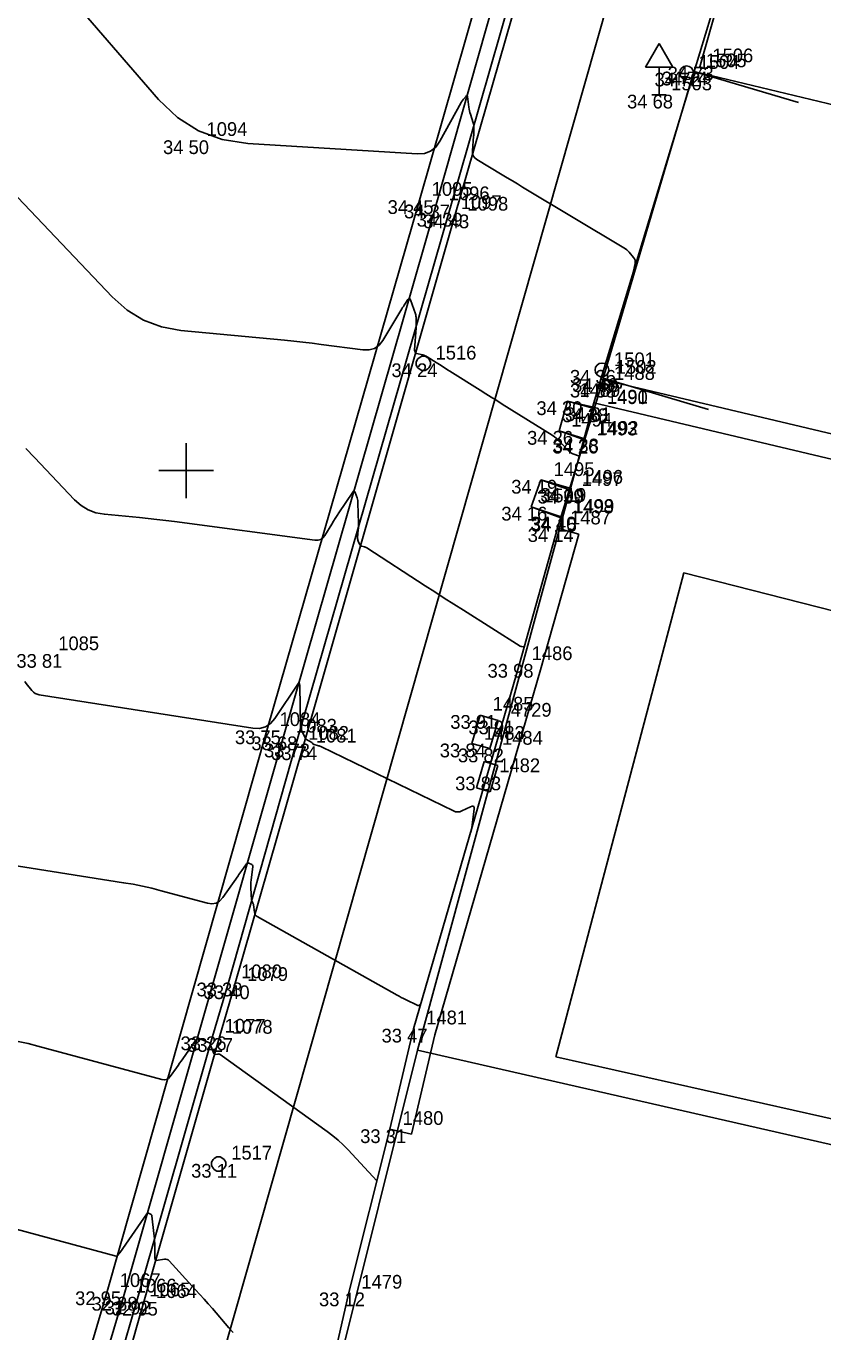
# Model space of a CAD drawing. Extents: x -702257 to -701487, y -1009871 to -1008841.
# Drawn here: x -701727.92 to -701713.41, y -1009265.68 to -1009241.91 of the extents above; entities that cross this region are included whole.
import ezdxf

# ---------------------------------------------------------------- set-up
doc = ezdxf.new("R2010")
doc.units = 0
for name, color, linetype in [('Ex_Major Contours', 7, 'Continuous'), ('Ex_Minor Contours', 7, 'Continuous'), ('Z_body', 7, 'Continuous'), ('Z_body_cisla', 7, 'Continuous'), ('Z_body_vysky_redukovane', 7, 'Continuous'), ('Z_budova', 7, 'Continuous'), ('Z_dopravni_znacky', 7, 'Continuous'), ('Z_hektometricka_sit', 7, 'Continuous'), ('Z_katastr_hranice', 7, 'Continuous'), ('Z_katastr_vnitrni_kresba', 7, 'Continuous'), ('Z_komunikace', 7, 'Continuous'), ('Z_obruba', 7, 'Continuous'), ('Z_pilire', 7, 'Continuous'), ('Z_ploty', 7, 'Continuous'), ('Z_rozhranni', 7, 'Continuous'), ('Z_site_kanalizace_znaky', 7, 'Continuous'), ('Z_site_vodovod_znaky', 7, 'Continuous'), ('Z_vstupy', 7, 'Continuous'), ('Z_zlabek', 7, 'Continuous')]:
    doc.layers.add(name, color=color, linetype=linetype)

# ---------------------------------------------------------------- blocks, each defined once
blk = doc.blocks.new('POINT_DISPLAY')
blk.add_line((0, 0), (0, 0))
blk = doc.blocks.new('Z15')
blk.add_circle((0, 0), 0.125)
blk = doc.blocks.new('Z666')
for p, q in [((-0.25, 0.13), (-0.25, -0.13)), ((0.25, 0.13), (-0.25, 0.13)), ((0.25, -0.13), (0.25, 0.13)), ((-0.25, -0.13), (0.25, -0.13))]:
    blk.add_line(p, q)
blk = doc.blocks.new('Z614')
for p, q in [((-0.13, 0.03), (-0.1, 0.08)), ((-0.13, -0.03), (-0.13, 0.03)), ((-0.1, 0.08), (-0.08, 0.1)), ((-0.08, 0.1), (-0.03, 0.13)), ((-0.03, 0.13), (0.03, 0.13)), ((0.03, 0.13), (0.08, 0.1)), ((0.08, 0.1), (0.1, 0.08)), ((0.1, 0.08), (0.13, 0.03)), ((0.13, 0.03), (0.13, -0.03)), ((-0.1, -0.08), (-0.13, -0.03)), ((-0.08, -0.1), (-0.1, -0.08)), ((-0.03, -0.13), (-0.08, -0.1)), ((0.03, -0.13), (-0.03, -0.13)), ((0.08, -0.1), (0.03, -0.13)), ((0.1, -0.08), (0.08, -0.1)), ((0.13, -0.03), (0.1, -0.08))]:
    blk.add_line(p, q)
blk = doc.blocks.new('Z527')
for p, q in [((0, 0.93), (-0.25, 0.5)), ((0.25, 0.5), (0, 0.93)), ((-0.25, 0.5), (0.25, 0.5)), ((0, 0), (0, 0.5)), ((-0.13, 0), (0.13, 0))]:
    blk.add_line(p, q)

msp = doc.modelspace()

# ---------------------------------------------------------------- linework, layer by layer
at = {"layer": 'Ex_Major Contours'}
for points in [[(-701718.844, -1009253.211), (-701718.891, -1009253.204), (-701718.899, -1009253.203), (-701718.906, -1009253.201), (-701718.913, -1009253.198), (-701718.92, -1009253.194), (-701719.952, -1009252.541), (-701720.127, -1009252.431), (-701720.3, -1009252.32), (-701720.474, -1009252.209), (-701720.647, -1009252.097), (-701721.711, -1009251.409), (-701721.721, -1009251.403), (-701721.732, -1009251.397), (-701721.743, -1009251.393), (-701721.755, -1009251.39), (-701721.802, -1009251.378), (-701721.814, -1009251.374), (-701721.823, -1009251.368), (-701721.831, -1009251.36), (-701721.837, -1009251.35), (-701721.868, -1009251.285), (-701721.874, -1009251.27), (-701721.877, -1009251.255), (-701721.879, -1009251.239), (-701721.879, -1009251.223), (-701721.867, -1009251.078), (-701721.865, -1009251.048), (-701721.864, -1009251.018), (-701721.864, -1009250.988), (-701721.864, -1009250.959), (-701721.872, -1009250.596), (-701721.874, -1009250.571), (-701721.877, -1009250.545), (-701721.883, -1009250.521), (-701721.89, -1009250.496), (-701721.924, -1009250.399), (-701721.933, -1009250.381), (-701721.944, -1009250.374), (-701721.956, -1009250.378), (-701721.969, -1009250.393), (-701722.221, -1009250.771), (-701722.254, -1009250.821), (-701722.287, -1009250.872), (-701722.319, -1009250.923), (-701722.35, -1009250.974), (-701722.475, -1009251.18), (-701722.51, -1009251.225), (-701722.551, -1009251.254), (-701722.6, -1009251.268), (-701722.657, -1009251.268), (-701725.213, -1009250.93), (-701725.372, -1009250.91), (-701725.532, -1009250.891), (-701725.691, -1009250.873), (-701725.851, -1009250.857), (-701726.49, -1009250.796), (-701726.643, -1009250.768), (-701726.785, -1009250.715), (-701726.914, -1009250.637), (-701727.031, -1009250.533), (-701727.762, -1009249.765), (-701727.918, -1009249.597)], [(-701730.306, -1009263.211), (-701726.274, -1009264.298), (-701726.266, -1009264.299), (-701726.26, -1009264.297), (-701726.254, -1009264.294), (-701726.249, -1009264.288), (-701726.22, -1009264.248), (-701726.211, -1009264.235), (-701725.715, -1009263.527), (-701725.709, -1009263.52), (-701725.702, -1009263.516), (-701725.694, -1009263.516), (-701725.685, -1009263.518), (-701725.647, -1009263.535), (-701725.639, -1009263.54), (-701725.632, -1009263.546), (-701725.628, -1009263.554), (-701725.626, -1009263.564), (-701725.587, -1009263.886), (-701725.582, -1009263.932), (-701725.578, -1009263.978), (-701725.575, -1009264.025), (-701725.574, -1009264.071), (-701725.569, -1009264.343), (-701725.568, -1009264.347), (-701725.568, -1009264.351), (-701725.567, -1009264.355), (-701725.565, -1009264.358), (-701725.559, -1009264.373), (-701725.557, -1009264.376), (-701725.555, -1009264.378), (-701725.552, -1009264.379), (-701725.548, -1009264.379), (-701725.398, -1009264.354), (-701725.372, -1009264.353), (-701725.349, -1009264.358), (-701725.328, -1009264.368), (-701725.309, -1009264.385), (-701724.828, -1009264.91), (-701724.751, -1009264.995), (-701724.674, -1009265.081), (-701724.598, -1009265.167), (-701724.522, -1009265.254), (-701724.221, -1009265.601), (-701724.144, -1009265.686)]]:
    msp.add_lwpolyline(points, dxfattribs=at)
at = {"layer": 'Ex_Minor Contours'}
for points in [[(-701727.258, -1009241.213), (-701725.503, -1009243.245), (-701725.16, -1009243.575), (-701724.775, -1009243.819), (-701724.348, -1009243.977), (-701723.878, -1009244.049), (-701720.793, -1009244.236), (-701720.663, -1009244.228), (-701720.55, -1009244.188), (-701720.456, -1009244.114), (-701720.38, -1009244.008), (-701719.996, -1009243.304), (-701719.987, -1009243.288), (-701719.977, -1009243.272), (-701719.966, -1009243.257), (-701719.954, -1009243.242), (-701719.905, -1009243.185), (-701719.894, -1009243.175), (-701719.886, -1009243.173), (-701719.88, -1009243.179), (-701719.876, -1009243.194), (-701719.854, -1009243.386), (-701719.849, -1009243.42), (-701719.843, -1009243.452), (-701719.835, -1009243.485), (-701719.825, -1009243.517), (-701719.774, -1009243.67), (-701719.768, -1009243.69), (-701719.764, -1009243.71), (-701719.762, -1009243.73), (-701719.761, -1009243.75), (-701719.762, -1009243.832), (-701719.763, -1009243.853), (-701719.764, -1009243.873), (-701719.765, -1009243.894), (-701719.766, -1009243.914), (-701719.789, -1009244.184), (-701719.787, -1009244.233), (-701719.773, -1009244.275), (-701719.747, -1009244.311), (-701719.708, -1009244.341), (-701719.245, -1009244.619), (-701719.153, -1009244.674), (-701719.061, -1009244.73), (-701718.969, -1009244.785), (-701718.877, -1009244.84), (-701717.029, -1009245.946), (-701717.003, -1009245.963), (-701716.978, -1009245.982), (-701716.956, -1009246.003), (-701716.935, -1009246.026), (-701716.855, -1009246.122), (-701716.838, -1009246.146), (-701716.828, -1009246.173), (-701716.825, -1009246.201), (-701716.828, -1009246.23), (-701716.925, -1009246.679)], [(-701717.838, -1009249.737), (-701717.963, -1009249.694), (-701717.984, -1009249.685), (-701718.002, -1009249.674), (-701718.02, -1009249.662), (-701718.035, -1009249.646), (-701718.194, -1009249.475), (-701718.227, -1009249.442), (-701718.261, -1009249.412), (-701718.297, -1009249.384), (-701718.336, -1009249.358), (-701719.245, -1009248.79), (-701719.345, -1009248.727), (-701719.445, -1009248.665), (-701719.545, -1009248.602), (-701719.645, -1009248.54), (-701720.202, -1009248.191), (-701720.243, -1009248.165), (-701720.285, -1009248.139), (-701720.388, -1009248.073), (-701720.451, -1009248.034), (-701720.612, -1009247.931), (-701720.631, -1009247.92), (-701720.651, -1009247.911), (-701720.671, -1009247.903), (-701720.693, -1009247.897), (-701720.809, -1009247.868), (-701720.816, -1009247.866), (-701720.821, -1009247.863), (-701720.825, -1009247.859), (-701720.828, -1009247.853), (-701720.84, -1009247.829), (-701720.842, -1009247.822), (-701720.844, -1009247.816), (-701720.845, -1009247.809), (-701720.845, -1009247.803), (-701720.813, -1009247.401), (-701720.812, -1009247.38), (-701720.811, -1009247.359), (-701720.81, -1009247.338), (-701720.811, -1009247.317), (-701720.813, -1009247.232), (-701720.814, -1009247.211), (-701720.817, -1009247.19), (-701720.821, -1009247.169), (-701720.827, -1009247.149), (-701720.917, -1009246.891), (-701720.926, -1009246.873), (-701720.936, -1009246.866), (-701720.948, -1009246.87), (-701720.962, -1009246.886), (-701721.018, -1009246.97), (-701721.032, -1009246.991), (-701721.046, -1009247.013), (-701721.059, -1009247.034), (-701721.072, -1009247.056), (-701721.42, -1009247.631), (-701721.489, -1009247.719), (-701721.573, -1009247.778), (-701721.671, -1009247.806), (-701721.783, -1009247.806), (-701722.542, -1009247.705), (-701722.709, -1009247.684), (-701722.875, -1009247.664), (-701723.042, -1009247.646), (-701723.209, -1009247.629), (-701725.095, -1009247.449), (-701725.45, -1009247.384), (-701725.778, -1009247.261), (-701726.077, -1009247.079), (-701726.347, -1009246.839), (-701728.649, -1009244.422)], [(-701718.013, -1009250.329), (-701718.016, -1009250.326), (-701718.016, -1009250.327), (-701718.107, -1009250.622), (-701718.129, -1009250.695), (-701718.172, -1009250.836), (-701718.174, -1009250.842), (-701718.176, -1009250.852)], [(-701727.938, -1009253.84), (-701727.913, -1009253.873), (-701727.81, -1009254.004), (-701727.783, -1009254.034), (-701727.751, -1009254.057), (-701727.716, -1009254.073), (-701727.677, -1009254.083), (-701723.789, -1009254.69), (-701723.667, -1009254.694), (-701723.558, -1009254.665), (-701723.464, -1009254.605), (-701723.384, -1009254.512), (-701722.954, -1009253.867), (-701722.951, -1009253.864), (-701722.949, -1009253.863), (-701722.946, -1009253.865), (-701722.944, -1009253.869), (-701722.937, -1009253.89), (-701722.935, -1009253.895), (-701722.934, -1009253.901), (-701722.933, -1009253.906), (-701722.933, -1009253.912), (-701722.916, -1009254.673), (-701722.916, -1009254.682), (-701722.917, -1009254.69), (-701722.917, -1009254.695), (-701722.915, -1009254.699), (-701722.83, -1009254.879), (-701722.829, -1009254.88), (-701722.825, -1009254.881), (-701722.778, -1009254.912), (-701722.757, -1009254.925), (-701722.714, -1009254.952), (-701722.71, -1009254.955), (-701722.706, -1009254.958), (-701722.703, -1009254.961), (-701722.7, -1009254.965), (-701722.687, -1009254.979), (-701722.684, -1009254.983), (-701722.68, -1009254.985), (-701722.676, -1009254.987), (-701722.671, -1009254.989), (-701722.592, -1009255.008), (-701722.578, -1009255.012), (-701722.564, -1009255.017), (-701722.55, -1009255.022), (-701722.536, -1009255.028), (-701720.135, -1009256.195), (-701720.097, -1009256.209), (-701720.058, -1009256.213), (-701720.019, -1009256.209), (-701719.98, -1009256.194), (-701719.825, -1009256.118), (-701719.792, -1009256.107), (-701719.77, -1009256.111), (-701719.759, -1009256.131), (-701719.758, -1009256.166), (-701719.798, -1009256.495), (-701719.799, -1009256.505), (-701719.801, -1009256.514), (-701719.803, -1009256.524), (-701719.805, -1009256.533), (-701719.818, -1009256.59)], [(-701720.748, -1009259.778), (-701720.746, -1009259.767), (-701720.742, -1009259.732), (-701720.742, -1009259.728), (-701720.743, -1009259.726), (-701720.746, -1009259.726), (-701720.749, -1009259.727), (-701720.766, -1009259.735), (-701720.77, -1009259.737), (-701720.774, -1009259.737), (-701720.778, -1009259.737), (-701720.782, -1009259.735), (-701721.006, -1009259.626), (-701721.045, -1009259.607), (-701721.083, -1009259.588), (-701721.121, -1009259.568), (-701721.158, -1009259.547), (-701723.708, -1009258.116), (-701723.728, -1009258.102), (-701723.743, -1009258.084), (-701723.753, -1009258.063), (-701723.758, -1009258.04), (-701723.775, -1009257.903), (-701723.776, -1009257.895), (-701723.778, -1009257.887), (-701723.781, -1009257.88), (-701723.785, -1009257.872), (-701723.8, -1009257.843), (-701723.804, -1009257.836), (-701723.807, -1009257.828), (-701723.808, -1009257.82), (-701723.809, -1009257.812), (-701723.825, -1009257.603), (-701723.826, -1009257.566), (-701723.826, -1009257.528), (-701723.824, -1009257.491), (-701723.82, -1009257.453), (-701723.787, -1009257.208), (-701723.787, -1009257.195), (-701723.79, -1009257.184), (-701723.797, -1009257.175), (-701723.808, -1009257.169), (-701723.859, -1009257.146), (-701723.871, -1009257.143), (-701723.882, -1009257.144), (-701723.892, -1009257.149), (-701723.901, -1009257.158), (-701723.987, -1009257.282), (-701724.004, -1009257.306), (-701724.022, -1009257.33), (-701724.039, -1009257.355), (-701724.056, -1009257.379), (-701724.335, -1009257.773), (-701724.392, -1009257.835), (-701724.457, -1009257.872), (-701724.531, -1009257.885), (-701724.614, -1009257.874), (-701725.455, -1009257.647), (-701725.624, -1009257.604), (-701725.795, -1009257.565), (-701725.967, -1009257.531), (-701726.139, -1009257.502), (-701728.206, -1009257.179)], [(-701728.058, -1009260.391), (-701727.88, -1009260.431), (-701727.703, -1009260.477), (-701725.444, -1009261.086), (-701725.399, -1009261.092), (-701725.358, -1009261.085), (-701725.323, -1009261.064), (-701725.292, -1009261.031), (-701725.178, -1009260.87), (-701725.149, -1009260.83), (-701725.121, -1009260.789), (-701725.093, -1009260.749), (-701725.064, -1009260.709), (-701724.83, -1009260.374), (-701724.811, -1009260.353), (-701724.789, -1009260.342), (-701724.764, -1009260.34), (-701724.736, -1009260.348), (-701724.566, -1009260.423), (-701724.563, -1009260.425), (-701724.562, -1009260.429), (-701724.561, -1009260.441), (-701724.56, -1009260.454), (-701724.559, -1009260.459), (-701724.494, -1009260.61), (-701724.489, -1009260.619), (-701724.482, -1009260.624), (-701724.474, -1009260.627), (-701724.465, -1009260.627), (-701724.422, -1009260.62), (-701724.412, -1009260.619), (-701724.402, -1009260.62), (-701724.393, -1009260.623), (-701724.384, -1009260.629), (-701722.434, -1009262.03), (-701722.332, -1009262.107), (-701722.234, -1009262.188), (-701722.141, -1009262.275), (-701722.051, -1009262.366), (-701721.527, -1009262.928)]]:
    msp.add_lwpolyline(points, dxfattribs=at)
at = {"layer": 'Z_budova'}
for p, q in [((-701715.76, -1009242.74), (-701717.41, -1009248.32)), ((-701713.85, -1009243.3), (-701715.76, -1009242.74)), ((-701717.41, -1009248.32), (-701715.49, -1009248.89))]:
    msp.add_line(p, q, dxfattribs=at)
at = {"layer": 'Z_hektometricka_sit'}
for p, q in [((-701725, -1009249.5), (-701725, -1009250.5)), ((-701725, -1009249.5), (-701725, -1009250.5)), ((-701725.5, -1009250), (-701724.5, -1009250)), ((-701725.5, -1009250), (-701724.5, -1009250))]:
    msp.add_line(p, q, dxfattribs=at)
at = {"layer": 'Z_katastr_hranice'}
for p, q in [((-701705.38, -1009199.53), (-701735.58, -1009305.62)), ((-701714.04, -1009237.1), (-701715.75, -1009242.74)), ((-701715.75, -1009242.74), (-701717.45, -1009248.34)), ((-701717.45, -1009248.34), (-701717.58, -1009248.77)), ((-701717.58, -1009248.77), (-701720.79, -1009260.55)), ((-701717.58, -1009248.77), (-701702.1, -1009252.43)), ((-701720.79, -1009260.55), (-701723.82, -1009272.69)), ((-701720.79, -1009260.55), (-701694.55, -1009266.54))]:
    msp.add_line(p, q, dxfattribs=at)
at = {"layer": 'Z_katastr_vnitrni_kresba'}
for p, q in [((-701715.75, -1009242.74), (-701708.04, -1009244.58)), ((-701701.98, -1009252), (-701717.45, -1009248.34)), ((-701715.94, -1009251.86), (-701718.27, -1009260.67)), ((-701710.58, -1009253.23), (-701715.94, -1009251.86)), ((-701718.27, -1009260.67), (-701703.41, -1009264.01))]:
    msp.add_line(p, q, dxfattribs=at)
at = {"layer": 'Z_komunikace'}
for p, q in [((-701719.01, -1009241.09), (-701720.22, -1009245.31)), ((-701723, -1009254.97), (-701720.22, -1009245.31)), ((-701724.23, -1009259.32), (-701723, -1009254.97)), ((-701724.52, -1009260.3), (-701724.23, -1009259.32)), ((-701725.9, -1009265.11), (-701724.52, -1009260.3)), ((-701725.9, -1009265.11), (-701727.56, -1009270.85))]:
    msp.add_line(p, q, dxfattribs=at)
at = {"layer": 'Z_obruba'}
for p, q in [((-701720.1, -1009245.34), (-701718.89, -1009241.13)), ((-701720.1, -1009245.34), (-701722.87, -1009255.02)), ((-701722.87, -1009255.02), (-701724.12, -1009259.37)), ((-701724.12, -1009259.37), (-701724.4, -1009260.33)), ((-701724.4, -1009260.33), (-701725.77, -1009265.13)), ((-701727.43, -1009270.89), (-701725.77, -1009265.13))]:
    msp.add_line(p, q, dxfattribs=at)
at = {"layer": 'Z_pilire'}
for p, q in [((-701719.65, -1009254.45), (-701719.8, -1009254.97)), ((-701719.65, -1009254.45), (-701719.32, -1009254.55)), ((-701719.47, -1009255.06), (-701719.32, -1009254.55)), ((-701719.8, -1009254.97), (-701719.47, -1009255.06))]:
    msp.add_line(p, q, dxfattribs=at)
at = {"layer": 'Z_ploty'}
for p, q in [((-701717.43, -1009248.42), (-701717.41, -1009248.32)), ((-701717.09, -1009248.5), (-701717.43, -1009248.42)), ((-701717.09, -1009248.5), (-701717.07, -1009248.42)), ((-701718.24, -1009251.05), (-701718.93, -1009253.52)), ((-701717.85, -1009251.16), (-701718.24, -1009251.05)), ((-701717.85, -1009251.16), (-701718.55, -1009253.63)), ((-701718.93, -1009253.52), (-701720.86, -1009260.16)), ((-701718.55, -1009253.63), (-701720.47, -1009260.27)), ((-701720.86, -1009260.16), (-701721.29, -1009261.99)), ((-701720.47, -1009260.27), (-701720.9, -1009262.08)), ((-701720.9, -1009262.08), (-701721.29, -1009261.99)), ((-701722.04, -1009264.96), (-701722.37, -1009266.42))]:
    msp.add_line(p, q, dxfattribs=at)
at = {"layer": 'Z_rozhranni'}
for p, q in [((-701718.21, -1009249.28), (-701718.06, -1009248.74)), ((-701718.06, -1009248.74), (-701717.57, -1009248.87)), ((-701717.56, -1009248.85), (-701718.06, -1009248.74)), ((-701718.21, -1009249.28), (-701717.75, -1009249.44)), ((-701717.74, -1009249.42), (-701718.21, -1009249.28)), ((-701718.72, -1009250.66), (-701718.54, -1009250.17)), ((-701718.54, -1009250.17), (-701718.02, -1009250.35)), ((-701718.01, -1009250.32), (-701718.54, -1009250.17)), ((-701718.17, -1009250.84), (-701718.72, -1009250.66)), ((-701718.18, -1009250.86), (-701718.72, -1009250.66))]:
    msp.add_line(p, q, dxfattribs=at)
at = {"layer": 'Z_vstupy'}
for p, q in [((-701715.65, -1009242.65), (-701715.3, -1009241.43)), ((-701717.43, -1009248.42), (-701718.24, -1009251.05)), ((-701721.29, -1009261.99), (-701722.04, -1009264.96))]:
    msp.add_line(p, q, dxfattribs=at)
at = {"layer": 'Z_zlabek'}
for p, q in [((-701720.75, -1009245.08), (-701718.2, -1009236.15)), ((-701717.91, -1009236.22), (-701720.45, -1009245.16)), ((-701720.75, -1009245.08), (-701723.53, -1009254.73)), ((-701723.23, -1009254.84), (-701720.45, -1009245.16)), ((-701723.53, -1009254.73), (-701726.44, -1009264.94)), ((-701726.14, -1009265.04), (-701723.23, -1009254.84)), ((-701726.44, -1009264.94), (-701728.12, -1009270.67)), ((-701727.88, -1009270.78), (-701726.14, -1009265.04))]:
    msp.add_line(p, q, dxfattribs=at)

# ---------------------------------------------------------------- block references
at = {"layer": 'Z_body'}
for p in [(-701715.89, -1009242.76), (-701715.76, -1009242.74), (-701715.65, -1009242.65), (-701716.39, -1009243.16), (-701724.86, -1009243.99), (-701720.75, -1009245.08), (-701720.45, -1009245.16), (-701720.22, -1009245.31), (-701720.1, -1009245.34), (-701720.68, -1009248.05), (-701717.43, -1009248.17), (-701717.43, -1009248.42), (-701717.41, -1009248.32), (-701718.06, -1009248.74), (-701717.57, -1009248.87), (-701717.56, -1009248.85), (-701718.21, -1009249.28), (-701717.75, -1009249.44), (-701717.74, -1009249.42), (-701718.54, -1009250.17), (-701718.02, -1009250.35), (-701718.01, -1009250.32), (-701718.72, -1009250.66), (-701718.18, -1009250.86), (-701718.17, -1009250.84), (-701718.24, -1009251.05), (-701727.55, -1009253.34), (-701718.93, -1009253.52), (-701719.65, -1009254.45), (-701719.32, -1009254.55), (-701723.53, -1009254.73), (-701723.23, -1009254.84), (-701723, -1009254.97), (-701722.87, -1009255.02), (-701719.8, -1009254.97), (-701719.47, -1009255.06), (-701719.52, -1009255.57), (-701724.23, -1009259.32), (-701724.12, -1009259.37), (-701720.86, -1009260.16), (-701724.52, -1009260.3), (-701724.4, -1009260.33), (-701721.29, -1009261.99), (-701724.41, -1009262.62), (-701726.44, -1009264.94), (-701726.14, -1009265.04), (-701725.9, -1009265.11), (-701725.77, -1009265.13), (-701722.04, -1009264.96)]:
    msp.add_blockref('POINT_DISPLAY', p, dxfattribs=at)
at = {"layer": 'Z_dopravni_znacky'}
msp.add_blockref('Z527', (-701716.39, -1009243.16), dxfattribs=at)
at = {"layer": 'Z_pilire', "rotation": 73.8}
msp.add_blockref('Z666', (-701719.52, -1009255.57), dxfattribs=at)
at = {"layer": 'Z_site_kanalizace_znaky'}
for p in [(-701715.89, -1009242.76), (-701717.43, -1009248.17)]:
    msp.add_blockref('Z15', p, dxfattribs=at)
at = {"layer": 'Z_site_vodovod_znaky'}
for p in [(-701720.68, -1009248.05), (-701724.41, -1009262.62)]:
    msp.add_blockref('Z614', p, dxfattribs=at)

# ---------------------------------------------------------------- texts
at = {"layer": 'Z_body_cisla'}
for s, p in [('1506', (-701715.42, -1009242.57)), ('1504', (-701715.67, -1009242.69)), ('1505', (-701715.54, -1009242.66)), ('1503', (-701716.17, -1009243.08)), ('1094', (-701724.63, -1009243.91)), ('1095', (-701720.53, -1009245)), ('1096', (-701720.22, -1009245.08)), ('1097', (-701720, -1009245.24)), ('1098', (-701719.88, -1009245.27)), ('1516', (-701720.46, -1009247.98)), ('1501', (-701717.21, -1009248.1)), ('1502', (-701717.18, -1009248.24)), ('1488', (-701717.21, -1009248.35)), ('1489', (-701717.84, -1009248.66)), ('1491', (-701717.34, -1009248.78)), ('1490', (-701717.34, -1009248.79)), ('1494', (-701717.99, -1009249.2)), ('1493', (-701717.53, -1009249.36)), ('1492', (-701717.51, -1009249.35)), ('1495', (-701718.31, -1009250.1)), ('1497', (-701717.8, -1009250.28)), ('1496', (-701717.79, -1009250.24)), ('1500', (-701718.5, -1009250.58)), ('1498', (-701717.96, -1009250.78)), ('1499', (-701717.95, -1009250.77)), ('1487', (-701718.01, -1009250.98)), ('1085', (-701727.33, -1009253.27)), ('1486', (-701718.71, -1009253.45)), ('1485', (-701719.42, -1009254.37)), ('4729', (-701719.09, -1009254.48)), ('1084', (-701723.3, -1009254.65)), ('1083', (-701723, -1009254.77)), ('1082', (-701722.78, -1009254.9)), ('1081', (-701722.64, -1009254.95)), ('1483', (-701719.58, -1009254.9)), ('1484', (-701719.25, -1009254.99)), ('1482', (-701719.3, -1009255.49)), ('1080', (-701724, -1009259.24)), ('1079', (-701723.89, -1009259.29)), ('1481', (-701720.63, -1009260.08)), ('1077', (-701724.3, -1009260.23)), ('1078', (-701724.17, -1009260.25)), ('1480', (-701721.06, -1009261.91)), ('1517', (-701724.18, -1009262.54)), ('1067', (-701726.21, -1009264.86)), ('1479', (-701721.81, -1009264.89)), ('1066', (-701725.92, -1009264.96)), ('1065', (-701725.67, -1009265.03)), ('1064', (-701725.55, -1009265.06))]:
    msp.add_text(s, height=0.25, dxfattribs=at).set_placement(p)
at = {"layer": 'Z_body_vysky_redukovane'}
for s, p in [('34 72', (-701716.473, -1009243.01)), ('34 74', (-701716.343, -1009242.99)), ('34 73', (-701716.233, -1009242.9)), ('34 68', (-701716.973, -1009243.41)), ('34 50', (-701725.422, -1009244.24)), ('34 45', (-701721.333, -1009245.33)), ('34 37', (-701721.033, -1009245.41)), ('34 39', (-701720.803, -1009245.56)), ('34 43', (-701720.683, -1009245.59)), ('34 24', (-701721.263, -1009248.3)), ('34 36', (-701718.013, -1009248.42)), ('34 38', (-701718.013, -1009248.67)), ('34 40', (-701717.973, -1009248.57)), ('34 30', (-701718.623, -1009248.99)), ('34 38', (-701718.153, -1009249.12)), ('34 31', (-701718.102, -1009249.1)), ('34 26', (-701718.793, -1009249.53)), ('34 26', (-701718.333, -1009249.69)), ('34 38', (-701718.323, -1009249.67)), ('34 19', (-701719.082, -1009250.42)), ('34 39', (-701718.603, -1009250.6)), ('34 19', (-701718.552, -1009250.57)), ('34 16', (-701719.262, -1009250.91)), ('34 40', (-701718.733, -1009251.09)), ('34 15', (-701718.722, -1009251.11)), ('34 14', (-701718.782, -1009251.3)), ('33 81', (-701728.092, -1009253.59)), ('33 98', (-701719.513, -1009253.77)), ('33 91', (-701720.192, -1009254.7)), ('33 91', (-701719.862, -1009254.8)), ('33 75', (-701724.113, -1009254.98)), ('33 68', (-701723.813, -1009255.09)), ('33 73', (-701723.583, -1009255.22)), ('33 74', (-701723.453, -1009255.27)), ('33 84', (-701720.383, -1009255.22)), ('33 82', (-701720.053, -1009255.31)), ('33 83', (-701720.103, -1009255.82)), ('33 38', (-701724.813, -1009259.57)), ('33 40', (-701724.682, -1009259.62)), ('33 47', (-701721.443, -1009260.41)), ('33 26', (-701725.103, -1009260.55)), ('33 27', (-701724.983, -1009260.58)), ('33 31', (-701721.832, -1009262.24)), ('33 11', (-701724.91, -1009262.87)), ('32 95', (-701727.023, -1009265.19)), ('32 88', (-701726.723, -1009265.29)), ('32 92', (-701726.483, -1009265.36)), ('32 95', (-701726.353, -1009265.38)), ('33 12', (-701722.582, -1009265.21))]:
    msp.add_text(s, height=0.25, dxfattribs=at).set_placement(p)

doc.saveas('drawing.dxf')
